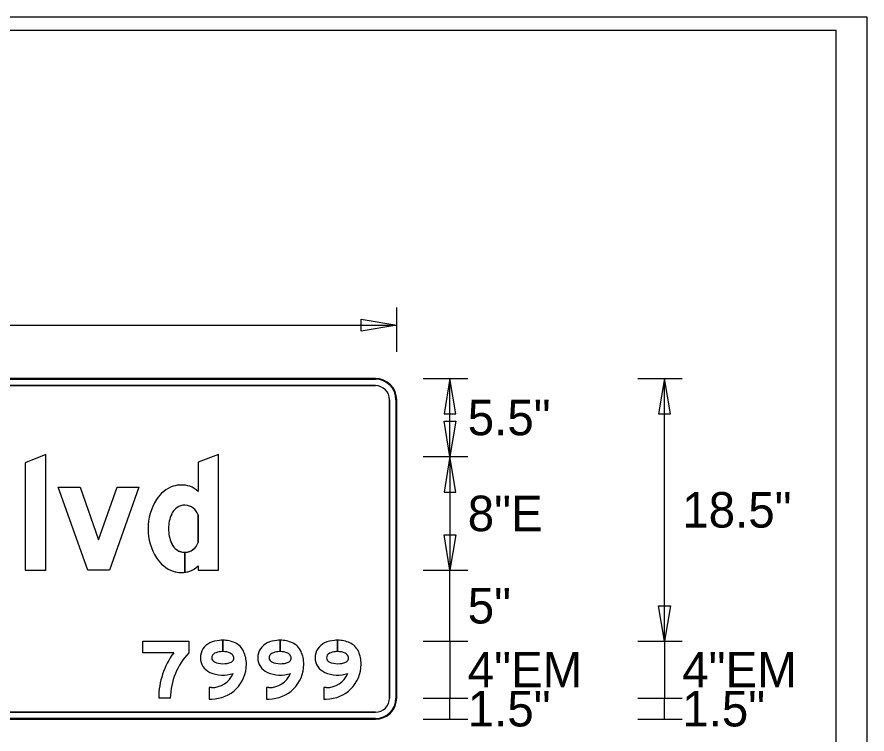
# Model space of a CAD drawing. Extents: x -998.8 to -961.2, y -2311.8 to -2287.8.
# Drawn here: x -966.202 to -961.216, y -2292.056 to -2287.849 of the extents above; entities that cross this region are included whole.
import ezdxf

# ---------------------------------------------------------------- set-up
doc = ezdxf.new("R2010")
doc.units = 0
for name, color, linetype in [('AdhocPoint_dp', 7, 'Continuous'), ('GSBWFill', 7, 'Continuous'), ('GSDims', 7, 'Continuous'), ('PlotBorder_dp', 7, 'Continuous'), ('SheetLinesMisc2_dp', 7, 'Continuous')]:
    doc.layers.add(name, color=color, linetype=linetype)

msp = doc.modelspace()

# ---------------------------------------------------------------- linework, layer by layer
at = {"layer": 'AdhocPoint_dp'}
for p, q in [((-964.1003, -2289.9701), (-971.8503, -2289.9701)), ((-964.1003, -2290.0118), (-971.8503, -2290.0118)), ((-964.0169, -2291.8451), (-964.0169, -2290.0951)), ((-963.9753, -2291.8451), (-963.9753, -2290.0951)), ((-965.1403, -2290.9327), (-965.1403, -2290.771)), ((-965.3033, -2291.8451), (-965.3713, -2291.8451)), ((-971.8503, -2291.9285), (-964.1003, -2291.9285)), ((-971.8503, -2291.9701), (-964.1003, -2291.9701))]:
    msp.add_line(p, q, dxfattribs=at)
for points in [[(-966.0336, -2291.0952), (-966.0336, -2290.4169), (-966.1536, -2290.4652), (-966.1536, -2291.0952)], [(-965.9603, -2290.6086), (-965.8329, -2290.6086), (-965.7236, -2290.9161), (-965.6143, -2290.6086), (-965.4869, -2290.6086), (-965.6599, -2291.0952), (-965.7873, -2291.0952)]]:
    msp.add_lwpolyline(points, close=True, dxfattribs=at)
for points in [[(-965.1403, -2291.0701), (-965.1403, -2291.0952), (-965.0203, -2291.0952), (-965.0203, -2290.4169), (-965.1403, -2290.4613), (-965.1403, -2290.6337)], [(-965.4636, -2291.5118), (-965.1936, -2291.5118), (-965.1936, -2291.5794)], [(-965.2834, -2291.5794), (-965.4636, -2291.5794), (-965.4636, -2291.5118)], [(-965.0614, -2291.7843), (-965.0755, -2291.7843), (-965.0755, -2291.851), (-965.0614, -2291.851)], [(-964.7248, -2291.7843), (-964.7388, -2291.7843), (-964.7388, -2291.851), (-964.7248, -2291.851)], [(-964.3881, -2291.7843), (-964.4022, -2291.7843), (-964.4022, -2291.851), (-964.3881, -2291.851)]]:
    msp.add_lwpolyline(points, dxfattribs=at)
for centre, radius, start, end in [((-964.1003, -2290.0951), 0.125, 0, 90), ((-964.1003, -2290.0951), 0.0833, 0, 90), ((-965.0311, -2291.6089), 0.0958, 114.6565, 180), ((-964.9992, -2291.6784), 0.1723, 95.0055, 114.6565), ((-964.9953, -2291.7232), 0.2173, 90, 95.0055), ((-964.9953, -2291.6819), 0.176, 65.9497, 90), ((-964.9644, -2291.6127), 0.1002, 24.3684, 65.9497), ((-964.6944, -2291.6089), 0.0958, 114.6565, 180), ((-964.6626, -2291.6784), 0.1723, 95.0055, 114.6565), ((-964.6586, -2291.7232), 0.2173, 90, 95.0055), ((-964.6586, -2291.6819), 0.176, 65.9497, 90), ((-964.6277, -2291.6127), 0.1002, 24.3684, 65.9497), ((-964.3578, -2291.6089), 0.0958, 114.6565, 180), ((-964.3259, -2291.6784), 0.1723, 95.0055, 114.6565), ((-964.322, -2291.7232), 0.2173, 90, 95.0055), ((-964.322, -2291.6819), 0.176, 65.9497, 90), ((-964.2911, -2291.6127), 0.1002, 24.3684, 65.9497), ((-964.9167, -2291.848), 0.4546, 143.7706, 179.6332), ((-964.9083, -2291.8526), 0.3951, 136.2358, 178.9165), ((-965.0311, -2291.6089), 0.0292, 114.6565, 180), ((-964.9992, -2291.6784), 0.1056, 95.0055, 114.6565), ((-964.9953, -2291.7232), 0.1506, 90, 95.0055), ((-964.9953, -2291.6819), 0.1093, 65.9497, 90), ((-964.9644, -2291.6127), 0.0335, 24.3684, 65.9497), ((-965.0388, -2291.6465), 0.1819, 0, 24.3684), ((-964.6944, -2291.6089), 0.0292, 114.6565, 180), ((-964.6626, -2291.6784), 0.1056, 95.0055, 114.6565), ((-964.6586, -2291.7232), 0.1506, 90, 95.0055), ((-964.6586, -2291.6819), 0.1093, 65.9497, 90), ((-964.6277, -2291.6127), 0.0335, 24.3684, 65.9497), ((-964.7022, -2291.6465), 0.1819, 0, 24.3684), ((-964.3578, -2291.6089), 0.0292, 114.6565, 180), ((-964.3259, -2291.6784), 0.1056, 95.0055, 114.6565), ((-964.322, -2291.7232), 0.1506, 90, 95.0055), ((-964.322, -2291.6819), 0.1093, 65.9497, 90), ((-964.2911, -2291.6127), 0.0335, 24.3684, 65.9497), ((-964.3655, -2291.6465), 0.1819, 0, 24.3684), ((-965.0333, -2291.6089), 0.0936, 180, 246.6168), ((-965.0333, -2291.6089), 0.0269, 180, 246.6168), ((-964.9942, -2291.5185), 0.1255, 246.6168, 292.3337), ((-964.9561, -2291.6111), 0.0253, 292.3337, 23.1249), ((-965.0388, -2291.6465), 0.1152, 23.1249, 24.3684), ((-964.6967, -2291.6089), 0.0936, 180, 246.6168), ((-964.6967, -2291.6089), 0.0269, 180, 246.6168), ((-964.6575, -2291.5185), 0.1255, 246.6168, 292.3337), ((-964.6195, -2291.6111), 0.0253, 292.3337, 23.1249), ((-964.7022, -2291.6465), 0.1152, 23.1249, 24.3684), ((-964.36, -2291.6089), 0.0936, 180, 246.6168), ((-964.36, -2291.6089), 0.0269, 180, 246.6168), ((-964.3209, -2291.5185), 0.1255, 246.6168, 292.3337), ((-964.2828, -2291.6111), 0.0253, 292.3337, 23.1249), ((-964.3655, -2291.6465), 0.1152, 23.1249, 24.3684), ((-965.0614, -2291.6465), 0.2045, 270, 0), ((-964.7248, -2291.6465), 0.2045, 270, 0), ((-964.3881, -2291.6465), 0.2045, 270, 0), ((-964.9942, -2291.5185), 0.1922, 246.6168, 287.9558), ((-965.0614, -2291.6465), 0.1378, 270, 336.5631), ((-964.6575, -2291.5185), 0.1922, 246.6168, 287.9558), ((-964.7248, -2291.6465), 0.1378, 270, 336.5631), ((-964.3209, -2291.5185), 0.1922, 246.6168, 287.9558), ((-964.3881, -2291.6465), 0.1378, 270, 336.5631), ((-964.1003, -2291.8451), 0.125, 270, 0), ((-964.1003, -2291.8451), 0.0833, 270, 0)]:
    msp.add_arc(centre, radius, start, end, dxfattribs=at)
for centre, major_axis, start_param, end_param in [((-965.2239, -2290.7806), (0, 0.1888), 0.33836, 1.013098), ((-965.2378, -2290.7623), (0, 0.1671), 5.986356, 6.580014), ((-965.2307, -2290.7213), (0, 0.1259), 5.481957, 5.944825), ((-965.1126, -2290.8519), (0, 0.321), 1.00845, 1.570796), ((-965.2187, -2290.7961), (0, 0.0823), 5.022168, 7.476818), ((-965.1034, -2290.8519), (0, 0.2102), 1.149006, 1.570796), ((-965.1126, -2290.8519), (0, 0.321), 1.570796, 2.133142), ((-965.1034, -2290.8519), (0, 0.2102), 1.570796, 1.992587), ((-965.2187, -2290.9076), (0, 0.0823), 1.94796, 4.40261), ((-965.2239, -2290.9231), (0, 0.1888), 2.128495, 2.803233), ((-965.2307, -2290.9825), (0, 0.1259), 3.479953, 3.942821), ((-965.2378, -2290.9415), (0, 0.1671), 2.844764, 3.438422)]:
    msp.add_ellipse(centre, major_axis=major_axis, ratio=0.999998, start_param=start_param, end_param=end_param, dxfattribs=at)
at = {"layer": 'GSBWFill'}
for p, q in [((-964.1003, -2289.9701), (-971.8503, -2289.9701)), ((-971.8503, -2290.0118), (-964.1003, -2290.0118)), ((-964.0169, -2290.0951), (-964.0169, -2291.8451)), ((-963.9753, -2291.8451), (-963.9753, -2290.0951)), ((-965.1403, -2290.771), (-965.1403, -2290.9327)), ((-965.2187, -2291.1075), (-965.2187, -2290.99)), ((-965.2186, -2290.99), (-965.2186, -2291.1075)), ((-965.3033, -2291.8451), (-965.3713, -2291.8451)), ((-964.1003, -2291.9285), (-971.8499, -2291.9285)), ((-971.8499, -2291.9701), (-964.1003, -2291.9701))]:
    msp.add_line(p, q, dxfattribs=at)
for points in [[(-966.0336, -2291.0952), (-966.0336, -2290.4169), (-966.1536, -2290.4652), (-966.1536, -2291.0952)], [(-965.9603, -2290.6086), (-965.8329, -2290.6086), (-965.7236, -2290.9161), (-965.6143, -2290.6086), (-965.4869, -2290.6086), (-965.6599, -2291.0952), (-965.7873, -2291.0952)]]:
    msp.add_lwpolyline(points, close=True, dxfattribs=at)
for points in [[(-965.1403, -2291.0701), (-965.1403, -2291.0952), (-965.0203, -2291.0952), (-965.0203, -2290.4169), (-965.1403, -2290.4613), (-965.1403, -2290.6337)], [(-965.4636, -2291.5118), (-965.1936, -2291.5118), (-965.1936, -2291.5794)], [(-965.2834, -2291.5794), (-965.4636, -2291.5794), (-965.4636, -2291.5118)], [(-964.9953, -2291.506), (-964.9953, -2291.5726)], [(-964.9953, -2291.5726), (-964.9953, -2291.506)], [(-964.6586, -2291.506), (-964.6586, -2291.5726)], [(-964.6586, -2291.5726), (-964.6586, -2291.506)], [(-964.322, -2291.506), (-964.322, -2291.5726)], [(-964.322, -2291.5726), (-964.322, -2291.506)], [(-965.0614, -2291.7843), (-965.0755, -2291.7843), (-965.0755, -2291.851), (-965.0614, -2291.851)], [(-964.7248, -2291.7843), (-964.7388, -2291.7843), (-964.7388, -2291.851), (-964.7248, -2291.851)], [(-964.3881, -2291.7843), (-964.4022, -2291.7843), (-964.4022, -2291.851), (-964.3881, -2291.851)]]:
    msp.add_lwpolyline(points, dxfattribs=at)
for centre, radius, start, end in [((-964.1003, -2290.0951), 0.125, 0, 90), ((-964.1003, -2290.0951), 0.0833, 0, 90), ((-965.0311, -2291.6089), 0.0958, 114.6565, 180), ((-964.9992, -2291.6784), 0.1723, 95.0055, 114.6565), ((-964.9953, -2291.7232), 0.2173, 90.0044, 95.0055), ((-964.9953, -2291.6819), 0.176, 65.9497, 90), ((-964.9644, -2291.6127), 0.1002, 24.3684, 65.9497), ((-964.6944, -2291.6089), 0.0958, 114.6565, 180), ((-964.6626, -2291.6784), 0.1723, 95.0055, 114.6565), ((-964.6586, -2291.7232), 0.2173, 90.0044, 95.0055), ((-964.6586, -2291.6819), 0.176, 65.9497, 90), ((-964.6277, -2291.6127), 0.1002, 24.3684, 65.9497), ((-964.3578, -2291.6089), 0.0958, 114.6565, 180), ((-964.3259, -2291.6784), 0.1723, 95.0055, 114.6565), ((-964.322, -2291.7232), 0.2173, 90.0044, 95.0055), ((-964.322, -2291.6819), 0.176, 65.9497, 90), ((-964.2911, -2291.6127), 0.1002, 24.3684, 65.9497), ((-964.9167, -2291.848), 0.4546, 143.7706, 179.6332), ((-964.9083, -2291.8526), 0.3951, 136.2358, 178.9165), ((-965.0311, -2291.6089), 0.0292, 114.6565, 180), ((-964.9992, -2291.6784), 0.1056, 95.0055, 114.6565), ((-964.9953, -2291.7232), 0.1506, 90.0063, 95.0055), ((-964.9953, -2291.6819), 0.1093, 65.9497, 90), ((-964.9644, -2291.6127), 0.0335, 24.3684, 65.9497), ((-965.0388, -2291.6465), 0.1819, 0, 24.3684), ((-964.6944, -2291.6089), 0.0292, 114.6565, 180), ((-964.6626, -2291.6784), 0.1056, 95.0055, 114.6565), ((-964.6586, -2291.7232), 0.1506, 90.0063, 95.0055), ((-964.6586, -2291.6819), 0.1093, 65.9497, 90), ((-964.6277, -2291.6127), 0.0335, 24.3684, 65.9497), ((-964.7022, -2291.6465), 0.1819, 0, 24.3684), ((-964.3578, -2291.6089), 0.0292, 114.6565, 180), ((-964.3259, -2291.6784), 0.1056, 95.0055, 114.6565), ((-964.322, -2291.7232), 0.1506, 90.0063, 95.0055), ((-964.322, -2291.6819), 0.1093, 65.9497, 90), ((-964.2911, -2291.6127), 0.0335, 24.3684, 65.9497), ((-964.3655, -2291.6465), 0.1819, 0, 24.3684), ((-965.0333, -2291.6089), 0.0936, 180, 246.6168), ((-965.0333, -2291.6089), 0.0269, 180, 246.6168), ((-964.9942, -2291.5185), 0.1255, 246.6168, 292.3337), ((-964.9561, -2291.6111), 0.0253, 292.3337, 23.1249), ((-965.0388, -2291.6465), 0.1152, 23.1249, 24.3684), ((-964.6967, -2291.6089), 0.0936, 180, 246.6168), ((-964.6967, -2291.6089), 0.0269, 180, 246.6168), ((-964.6575, -2291.5185), 0.1255, 246.6168, 292.3337), ((-964.6195, -2291.6111), 0.0253, 292.3337, 23.1249), ((-964.7022, -2291.6465), 0.1152, 23.1249, 24.3684), ((-964.36, -2291.6089), 0.0936, 180, 246.6168), ((-964.36, -2291.6089), 0.0269, 180, 246.6168), ((-964.3209, -2291.5185), 0.1255, 246.6168, 292.3337), ((-964.2828, -2291.6111), 0.0253, 292.3337, 23.1249), ((-964.3655, -2291.6465), 0.1152, 23.1249, 24.3684), ((-965.0614, -2291.6465), 0.2045, 270, 0), ((-964.7248, -2291.6465), 0.2045, 270, 0), ((-964.3881, -2291.6465), 0.2045, 270, 0), ((-964.9942, -2291.5185), 0.1922, 246.6168, 287.9558), ((-965.0614, -2291.6465), 0.1378, 270, 336.5631), ((-964.6575, -2291.5185), 0.1922, 246.6168, 287.9558), ((-964.7248, -2291.6465), 0.1378, 270, 336.5631), ((-964.3209, -2291.5185), 0.1922, 246.6168, 287.9558), ((-964.3881, -2291.6465), 0.1378, 270, 336.5631), ((-964.1003, -2291.8451), 0.125, 270, 0), ((-964.1003, -2291.8451), 0.0833, 270, 0)]:
    msp.add_arc(centre, radius, start, end, dxfattribs=at)
for centre, major_axis, start_param, end_param in [((-965.2239, -2290.7806), (0, 0.1888), 0.33836, 1.013098), ((-965.2378, -2290.7623), (0, 0.1671), 5.986356, 6.580014), ((-965.2307, -2290.7213), (0, 0.1259), 5.481957, 5.944825), ((-965.1126, -2290.8519), (0, 0.321), 1.00845, 1.570796), ((-965.2187, -2290.7961), (0, 0.0823), 5.022168, 7.476818), ((-965.1034, -2290.8519), (0, 0.2102), 1.149006, 1.570796), ((-965.1126, -2290.8519), (0, 0.321), 1.570796, 2.133142), ((-965.1034, -2290.8519), (0, 0.2102), 1.570796, 1.992587), ((-965.2187, -2290.9076), (0, 0.0823), 1.94796, 3.141593), ((-965.2187, -2290.9076), (0, 0.0823), 3.141998, 4.40261), ((-965.2239, -2290.9231), (0, 0.1888), 2.128495, 2.803233), ((-965.2307, -2290.9825), (0, 0.1259), 3.479953, 3.942821), ((-965.2378, -2290.9415), (0, 0.1671), 2.844764, 3.25621), ((-965.2378, -2290.9415), (0, 0.1671), 3.256411, 3.438422)]:
    msp.add_ellipse(centre, major_axis=major_axis, ratio=0.999998, start_param=start_param, end_param=end_param, dxfattribs=at)
at = {"layer": 'GSDims'}
for p, q in [((-963.9753, -2289.8139), (-963.9753, -2289.5534)), ((-971.9753, -2289.6576), (-963.9753, -2289.6576)), ((-963.819, -2289.9701), (-963.5586, -2289.9701)), ((-963.6628, -2290.4286), (-963.6628, -2289.9701)), ((-962.5605, -2289.9701), (-962.3001, -2289.9701)), ((-962.4043, -2291.5118), (-962.4043, -2289.9701)), ((-963.819, -2290.4286), (-963.5586, -2290.4286)), ((-963.819, -2290.4286), (-963.5586, -2290.4286)), ((-963.6628, -2290.4286), (-963.6628, -2291.0952)), ((-963.819, -2291.0952), (-963.5586, -2291.0952)), ((-963.819, -2291.0952), (-963.5586, -2291.0952)), ((-963.6628, -2291.5118), (-963.6628, -2291.0952)), ((-963.819, -2291.5118), (-963.5586, -2291.5118)), ((-963.819, -2291.5118), (-963.5586, -2291.5118)), ((-963.6628, -2291.5118), (-963.6628, -2291.8451)), ((-962.5605, -2291.5118), (-962.3001, -2291.5118)), ((-962.5605, -2291.5118), (-962.3001, -2291.5118)), ((-962.4043, -2291.5118), (-962.4043, -2291.8451)), ((-963.819, -2291.8451), (-963.5586, -2291.8451)), ((-963.819, -2291.8451), (-963.5586, -2291.8451)), ((-963.6628, -2291.9701), (-963.6628, -2291.8451)), ((-962.5605, -2291.8451), (-962.3001, -2291.8451)), ((-962.5605, -2291.8451), (-962.3001, -2291.8451)), ((-962.4043, -2291.9701), (-962.4043, -2291.8451)), ((-963.819, -2291.9701), (-963.5586, -2291.9701)), ((-962.5605, -2291.9701), (-962.3001, -2291.9701))]:
    msp.add_line(p, q, dxfattribs=at)
for points in [[(-963.9753, -2289.6576), (-964.1836, -2289.6923), (-964.1836, -2289.6229)], [(-963.6628, -2289.9701), (-963.6975, -2290.1784), (-963.628, -2290.1784)], [(-962.4043, -2289.9701), (-962.439, -2290.1784), (-962.3695, -2290.1784)], [(-963.6628, -2290.4286), (-963.6975, -2290.2202), (-963.628, -2290.2202)], [(-963.6628, -2290.4286), (-963.6975, -2290.6369), (-963.628, -2290.6369)], [(-963.6628, -2291.0952), (-963.6975, -2290.8869), (-963.628, -2290.8869)], [(-962.4043, -2291.5118), (-962.439, -2291.3035), (-962.3695, -2291.3035)]]:
    msp.add_lwpolyline(points, close=True, dxfattribs=at)
at = {"layer": 'PlotBorder_dp'}
for p, q in [((-964.1003, -2289.9701), (-971.8503, -2289.9701)), ((-964.1003, -2289.9701), (-971.8503, -2289.9701)), ((-964.1003, -2289.9701), (-971.8503, -2289.9701)), ((-971.8503, -2289.9743), (-964.1003, -2289.9743)), ((-971.8503, -2290.0118), (-964.1003, -2290.0118)), ((-964.0169, -2290.0951), (-964.0169, -2291.8451)), ((-963.9794, -2290.0951), (-963.9794, -2291.8451)), ((-963.9753, -2291.8451), (-963.9753, -2290.0951)), ((-963.9753, -2291.8451), (-963.9753, -2290.0951)), ((-963.9753, -2291.8451), (-963.9753, -2290.0951)), ((-965.1403, -2290.771), (-965.1403, -2290.9327)), ((-965.2187, -2291.1075), (-965.2187, -2290.99)), ((-965.2186, -2290.99), (-965.2186, -2291.1075)), ((-965.3033, -2291.8451), (-965.3713, -2291.8451)), ((-964.1003, -2291.9285), (-971.8499, -2291.9285)), ((-971.8503, -2291.9701), (-964.1003, -2291.9701)), ((-964.1003, -2291.966), (-971.8502, -2291.966)), ((-971.8502, -2291.9701), (-964.1003, -2291.9701)), ((-971.8499, -2291.9701), (-964.1003, -2291.9701))]:
    msp.add_line(p, q, dxfattribs=at)
for points in [[(-966.0336, -2291.0952), (-966.0336, -2290.4169), (-966.1536, -2290.4652), (-966.1536, -2291.0952)], [(-965.9603, -2290.6086), (-965.8329, -2290.6086), (-965.7236, -2290.9161), (-965.6143, -2290.6086), (-965.4869, -2290.6086), (-965.6599, -2291.0952), (-965.7873, -2291.0952)]]:
    msp.add_lwpolyline(points, close=True, dxfattribs=at)
for points in [[(-965.1403, -2291.0701), (-965.1403, -2291.0952), (-965.0203, -2291.0952), (-965.0203, -2290.4169), (-965.1403, -2290.4613), (-965.1403, -2290.6337)], [(-965.4636, -2291.5118), (-965.1936, -2291.5118), (-965.1936, -2291.5794)], [(-965.2834, -2291.5794), (-965.4636, -2291.5794), (-965.4636, -2291.5118)], [(-964.9953, -2291.506), (-964.9953, -2291.5726)], [(-964.9953, -2291.5726), (-964.9953, -2291.506)], [(-964.6586, -2291.506), (-964.6586, -2291.5726)], [(-964.6586, -2291.5726), (-964.6586, -2291.506)], [(-964.322, -2291.506), (-964.322, -2291.5726)], [(-964.322, -2291.5726), (-964.322, -2291.506)], [(-965.0614, -2291.7843), (-965.0755, -2291.7843), (-965.0755, -2291.851), (-965.0614, -2291.851)], [(-964.7248, -2291.7843), (-964.7388, -2291.7843), (-964.7388, -2291.851), (-964.7248, -2291.851)], [(-964.3881, -2291.7843), (-964.4022, -2291.7843), (-964.4022, -2291.851), (-964.3881, -2291.851)]]:
    msp.add_lwpolyline(points, dxfattribs=at)
for centre, radius, start, end in [((-964.1003, -2290.0951), 0.125, 0, 90), ((-964.1003, -2290.0951), 0.125, 0, 90), ((-964.1003, -2290.0951), 0.125, 0, 90), ((-964.1003, -2290.0951), 0.1208, 0, 90), ((-964.1003, -2290.0951), 0.0833, 0, 90), ((-965.0311, -2291.6089), 0.0958, 114.6565, 180), ((-964.9992, -2291.6784), 0.1723, 95.0055, 114.6565), ((-964.9953, -2291.7232), 0.2173, 90.0044, 95.0055), ((-964.9953, -2291.6819), 0.176, 65.9497, 90), ((-964.9644, -2291.6127), 0.1002, 24.3684, 65.9497), ((-964.6944, -2291.6089), 0.0958, 114.6565, 180), ((-964.6626, -2291.6784), 0.1723, 95.0055, 114.6565), ((-964.6586, -2291.7232), 0.2173, 90.0044, 95.0055), ((-964.6586, -2291.6819), 0.176, 65.9497, 90), ((-964.6277, -2291.6127), 0.1002, 24.3684, 65.9497), ((-964.3578, -2291.6089), 0.0958, 114.6565, 180), ((-964.3259, -2291.6784), 0.1723, 95.0055, 114.6565), ((-964.322, -2291.7232), 0.2173, 90.0044, 95.0055), ((-964.322, -2291.6819), 0.176, 65.9497, 90), ((-964.2911, -2291.6127), 0.1002, 24.3684, 65.9497), ((-964.9167, -2291.848), 0.4546, 143.7706, 179.6332), ((-964.9083, -2291.8526), 0.3951, 136.2358, 178.9165), ((-965.0311, -2291.6089), 0.0292, 114.6565, 180), ((-964.9992, -2291.6784), 0.1056, 95.0055, 114.6565), ((-964.9953, -2291.7232), 0.1506, 90.0063, 95.0055), ((-964.9953, -2291.6819), 0.1093, 65.9497, 90), ((-964.9644, -2291.6127), 0.0335, 24.3684, 65.9497), ((-965.0388, -2291.6465), 0.1819, 360, 24.3684), ((-964.6944, -2291.6089), 0.0292, 114.6565, 180), ((-964.6626, -2291.6784), 0.1056, 95.0055, 114.6565), ((-964.6586, -2291.7232), 0.1506, 90.0063, 95.0055), ((-964.6586, -2291.6819), 0.1093, 65.9497, 90), ((-964.6277, -2291.6127), 0.0335, 24.3684, 65.9497), ((-964.7022, -2291.6465), 0.1819, 360, 24.3684), ((-964.3578, -2291.6089), 0.0292, 114.6565, 180), ((-964.3259, -2291.6784), 0.1056, 95.0055, 114.6565), ((-964.322, -2291.7232), 0.1506, 90.0063, 95.0055), ((-964.322, -2291.6819), 0.1093, 65.9497, 90), ((-964.2911, -2291.6127), 0.0335, 24.3684, 65.9497), ((-964.3655, -2291.6465), 0.1819, 360, 24.3684), ((-965.0333, -2291.6089), 0.0936, 180, 246.6168), ((-965.0333, -2291.6089), 0.0269, 180, 246.6168), ((-964.9942, -2291.5185), 0.1255, 246.6168, 292.3337), ((-964.9561, -2291.6111), 0.0253, 292.3337, 23.1249), ((-965.0388, -2291.6465), 0.1152, 23.1249, 24.3684), ((-964.6967, -2291.6089), 0.0936, 180, 246.6168), ((-964.6967, -2291.6089), 0.0269, 180, 246.6168), ((-964.6575, -2291.5185), 0.1255, 246.6168, 292.3337), ((-964.6195, -2291.6111), 0.0253, 292.3337, 23.1249), ((-964.7022, -2291.6465), 0.1152, 23.1249, 24.3684), ((-964.36, -2291.6089), 0.0936, 180, 246.6168), ((-964.36, -2291.6089), 0.0269, 180, 246.6168), ((-964.3209, -2291.5185), 0.1255, 246.6168, 292.3337), ((-964.2828, -2291.6111), 0.0253, 292.3337, 23.1249), ((-964.3655, -2291.6465), 0.1152, 23.1249, 24.3684), ((-965.0614, -2291.6465), 0.2045, 270, 0), ((-964.7248, -2291.6465), 0.2045, 270, 0), ((-964.3881, -2291.6465), 0.2045, 270, 0), ((-964.9942, -2291.5185), 0.1922, 246.6168, 287.9558), ((-965.0614, -2291.6465), 0.1378, 270, 336.5631), ((-964.6575, -2291.5185), 0.1922, 246.6168, 287.9558), ((-964.7248, -2291.6465), 0.1378, 270, 336.5631), ((-964.3209, -2291.5185), 0.1922, 246.6168, 287.9558), ((-964.3881, -2291.6465), 0.1378, 270, 336.5631), ((-964.1003, -2291.8451), 0.125, 270, 0), ((-964.1003, -2291.8451), 0.125, 270, 0), ((-964.1003, -2291.8451), 0.0833, 270, 0), ((-964.1003, -2291.8451), 0.125, 270, 0), ((-964.1003, -2291.8451), 0.1208, 270, 0)]:
    msp.add_arc(centre, radius, start, end, dxfattribs=at)
for centre, major_axis, start_param, end_param in [((-965.2239, -2290.7806), (0, 0.1888), 0.33836, 1.013098), ((-965.2378, -2290.7623), (0, 0.1671), 5.986356, 6.580014), ((-965.2307, -2290.7213), (0, 0.1259), 5.481957, 5.944825), ((-965.1126, -2290.8519), (0, 0.321), 1.00845, 1.570796), ((-965.2187, -2290.7961), (0, 0.0823), 5.022168, 7.476818), ((-965.1034, -2290.8519), (0, 0.2102), 1.149006, 1.570796), ((-965.1126, -2290.8519), (0, 0.321), 1.570796, 2.133142), ((-965.1034, -2290.8519), (0, 0.2102), 1.570796, 1.992587), ((-965.2187, -2290.9076), (0, 0.0823), 1.94796, 3.141593), ((-965.2187, -2290.9076), (0, 0.0823), 3.141998, 4.40261), ((-965.2239, -2290.9231), (0, 0.1888), 2.128495, 2.803233), ((-965.2307, -2290.9825), (0, 0.1259), 3.479953, 3.942821), ((-965.2378, -2290.9415), (0, 0.1671), 2.844764, 3.25621), ((-965.2378, -2290.9415), (0, 0.1671), 3.256411, 3.438422)]:
    msp.add_ellipse(centre, major_axis=major_axis, ratio=0.999998, start_param=start_param, end_param=end_param, dxfattribs=at)
at = {"layer": 'SheetLinesMisc2_dp'}
for p, q in [((-998.8259, -2287.8491), (-961.2164, -2287.8491)), ((-961.2164, -2311.2608), (-961.2164, -2287.8493)), ((-974.1876, -2287.9271), (-961.3963, -2287.9271)), ((-961.3963, -2294.1578), (-961.3963, -2287.9271))]:
    msp.add_line(p, q, dxfattribs=at)

# ---------------------------------------------------------------- texts
at = {"layer": 'GSDims'}
for s, p in [('5.5"', (-963.5586, -2290.3035)), ('18.5"', (-962.3001, -2290.8451)), ('8"E', (-963.5586, -2290.8661)), ('5"', (-963.5586, -2291.4077)), ('4"EM', (-963.5586, -2291.7826)), ('4"EM', (-962.3001, -2291.7826)), ('1.5"', (-963.5586, -2292.0118)), ('1.5"', (-962.3001, -2292.0118))]:
    msp.add_text(s, height=0.20833, dxfattribs=at).set_placement(p)

doc.saveas('drawing.dxf')
